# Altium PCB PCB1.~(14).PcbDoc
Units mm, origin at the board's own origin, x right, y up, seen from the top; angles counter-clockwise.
Board outline 152.4 x 101.6 mm, 2 copper layers (Top Layer, Bottom Layer); 19 components, 17 nets, 64 pads, 4 vias.
Unrouted connection lines stored in the file: 1.
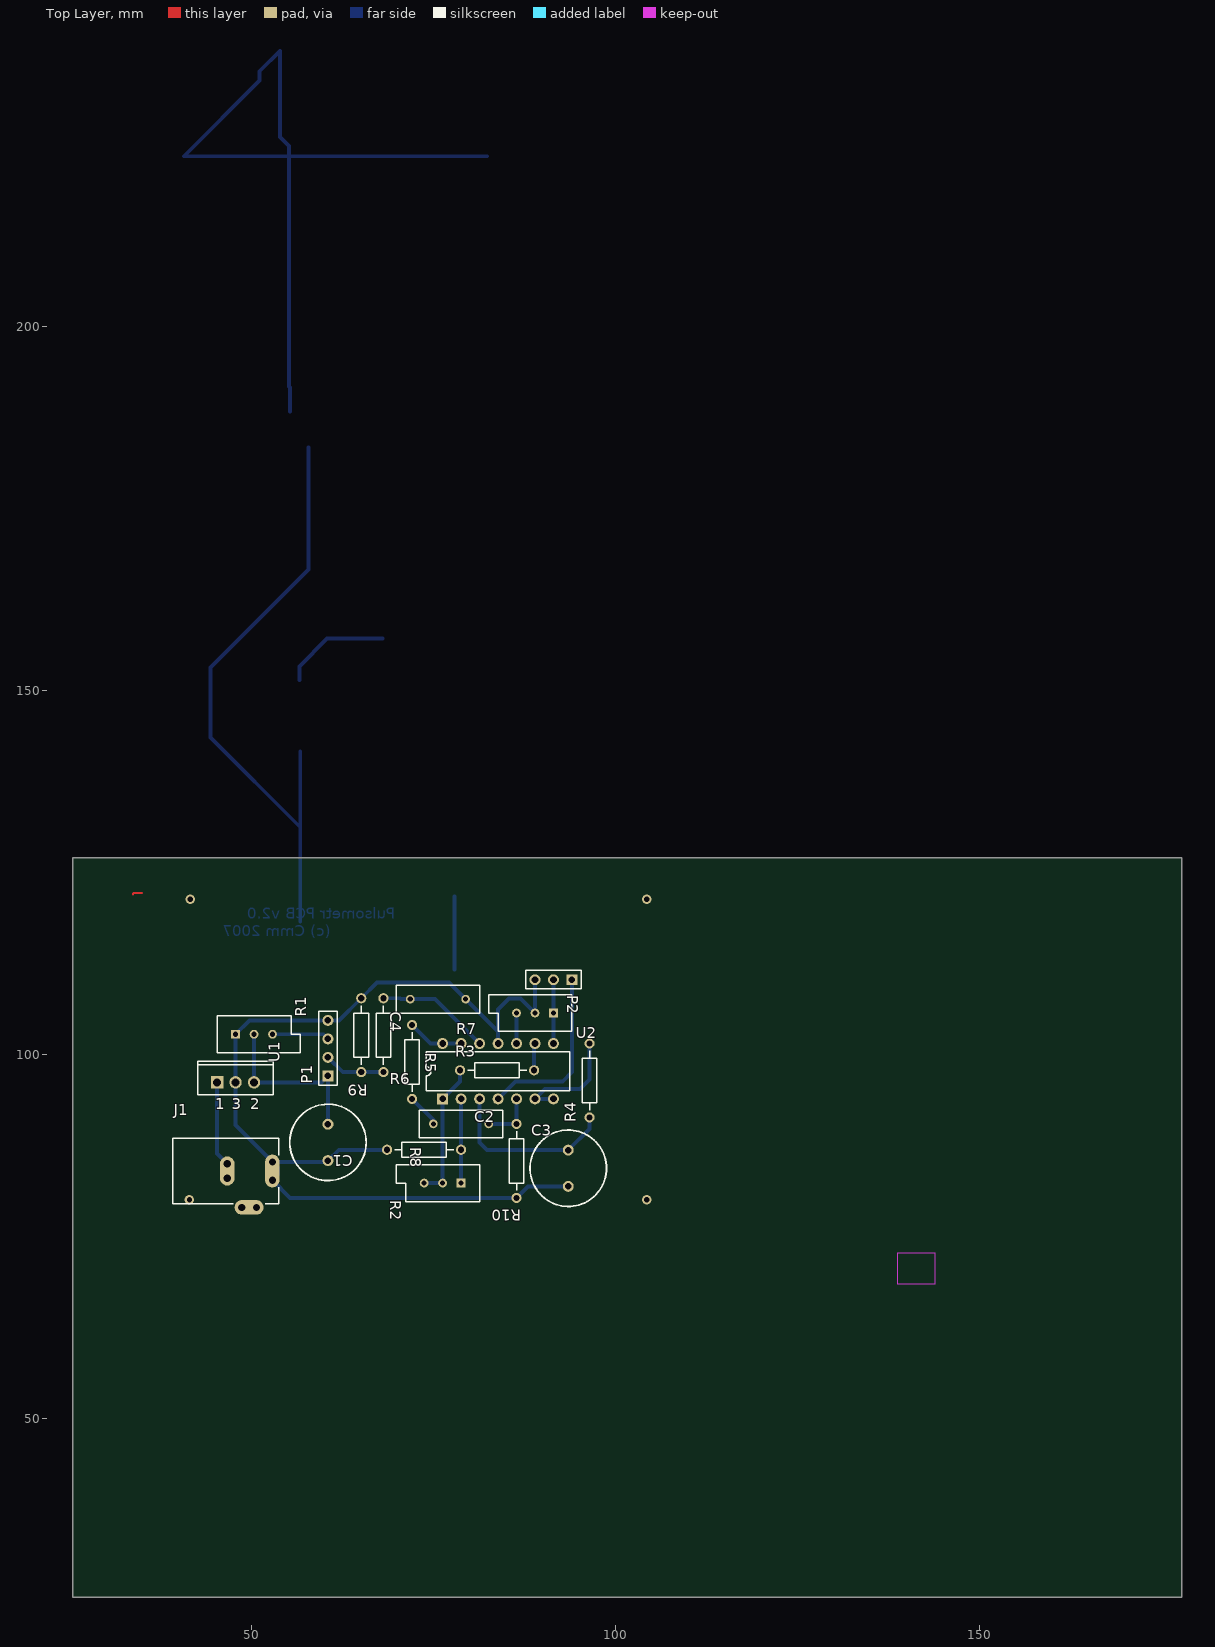
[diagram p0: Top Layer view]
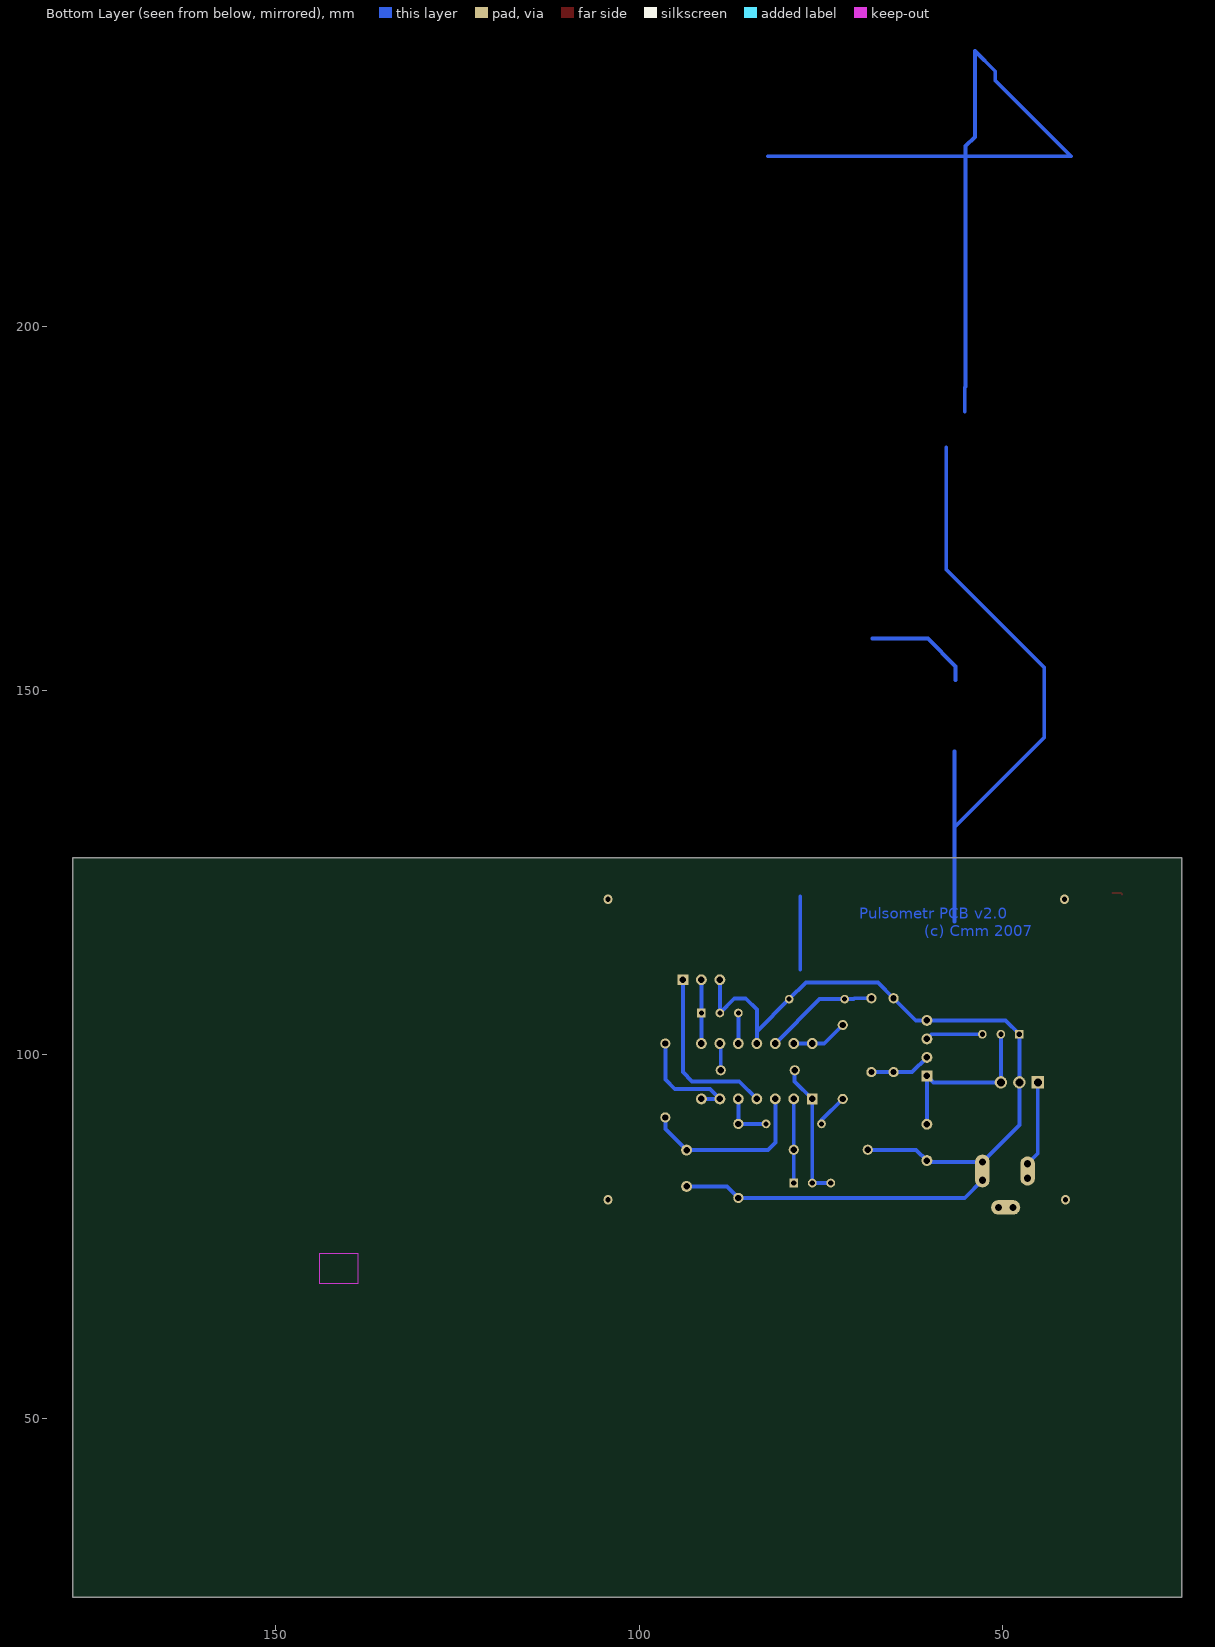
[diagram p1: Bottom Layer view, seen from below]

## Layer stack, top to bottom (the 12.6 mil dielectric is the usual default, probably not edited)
Top Layer: signal copper 0.0356
Dielectric: dielectric 0.32, FR-4, Dk 4.8
Bottom Layer: signal copper 0.0356

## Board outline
25.4,25.4 177.8,25.4 177.8,127 25.4,127

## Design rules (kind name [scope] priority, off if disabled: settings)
Clearance [All] p1: gap=0.254
ComponentClearance [All] p1: gap=0.254 collisioncheckmode=3 verticalgap=0.254
PolygonConnect [All] p1: connectstyle=Relief reliefconductorwidth=0.254 reliefentries=4 polygonreliefangle="90 Angle"
RoomDefinition Sheet1 [InComponentClass('Sheet1')] p1: confinementstyle=ConfineIn formatcopy=TRUE lockcomponents=FALSE outline 37.719,71.628 116.332,71.628 116.332,121.539 37.719,121.539
RoutingTopology [All] p1: topology=Daisy_Simple
RoutingVias [All] p1: holewidth=0.711 width=2 viastyle="Through Hole" minholewidth=0.711 minwidth=1.27 maxholewidth=0.711 maxwidth=2.27
SolderMaskExpansion [All] p1: expansion=0.102
TestPointUsage [All] p1: valid=0 allowmultiple=FALSE
Testpoint [All] p1: side=15 testpointundercomponent=TRUE minsize=1.016 maxsize=2.54 preferedsize=1.524 minholesize=0 maxholesize=1.016 preferedholesize=0.813 testpointgrid=0.025 style=1023 order=0123456789
Width [All] p1: maxlimit=1254 minlimit=0.254 preferedwidth=0.254 toplayer_maxwidth=1.254 toplayer_prefwidth=0.54 bottomlayer_minwidth=0.54 bottomlayer_prefwidth=0.54 minimp=50.000000 maximp=50.000000 favimp=50.000000
17 further rules are at their usual default settings.

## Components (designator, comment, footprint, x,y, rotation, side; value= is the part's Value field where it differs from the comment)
C1 "Cap Pol1" RB5-10.5 60.452,87.884 r90 top
C2 "Cap" RAD-0.3 78.74,90.424 r180 top
C3 "Cap Pol1" RB5-10.5 93.472,84.328 r270 top
C4 "Cap" RAD-0.3 75.565,107.569 r180 top
J1 "PWR2.5" KLD-0202 39.116,83.947 r0 top
P1 "Header 4" HDR1X4 60.452,97.028 r90 top
P2 "Header 3" HDR1X3 93.98,110.236 r180 top
R1 "RPot" VR5 50.292,102.743 r0 top
R2 "RPot" VR5 76.2,82.296 r180 top
R3 "Res2" AXIAL-0.4 83.693,97.79 r180 top
R4 "Res2" AXIAL-0.4 96.393,96.393 r90 top
R5 "Res2" AXIAL-0.4 72.009,98.933 r90 top
R6 "Res2" AXIAL-0.4 68.072,102.616 r270 top
R7 "RPot" VR5 88.9,105.664 r180 top
R8 "Res2" AXIAL-0.4 73.66,86.868 r180 top
R9 "Res2" AXIAL-0.4 65.024,102.616 r270 top
R10 "Res2" AXIAL-0.4 86.36,85.344 r270 top
U1 "L7812ABV" TO220ABN 47.752,96.139 r0 top
U2 "LM324AN" N14A 83.82,97.663 r0 top

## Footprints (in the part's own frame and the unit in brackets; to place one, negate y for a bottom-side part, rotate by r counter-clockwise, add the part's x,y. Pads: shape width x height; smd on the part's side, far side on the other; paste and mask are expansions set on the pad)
AXIAL-0.4 [mm] "Resistor; 2 Leads"
  round 1.4 hole 0.85: 1(-5.08,0) 2(5.08,0)
  silkscreen extent -4.06,-1.02 4.06,1.02
HDR1X3 [mm] "Connector; Header; 3 Position"
  rect 1.5x1.5 hole 0.9: 1(0,0)
  round 1.5 hole 0.9: 2(2.54,0) 3(5.08,0)
  silkscreen extent -1.27,-1.27 6.35,1.27
HDR1X4 [mm] "Connector; Header; 4 Position"
  rect 1.5x1.5 hole 0.9: 1(0,0)
  round 1.5 hole 0.9: 2(2.54,0) 3(5.08,0) 4(7.62,0)
  silkscreen extent -1.27,-1.27 8.89,1.27
KLD-0202 [mm] "DC Power Jack, 2.5mm, KLD Series, PCB Mount"
  oval 2x4.5 all layers, no hole: 1(13.7,0)
  round 1.5 hole 1: 1A(13.7,-1.25) 1B(13.7,1.25) 2A(7.5,-1) 2B(7.5,1) 3A(9.5,-5) 3B(11.5,-5)
  oval 2x4 all layers, no hole: 2(7.5,0)
  oval 4x2 all layers, no hole: 3(10.5,-5)
  silkscreen extent 0,-4.5 14.6,4.5
N14A [mm] "DIP; 14 Leads; Row Spacing 7.62 mm; Pitch 2.54 mm"
  rect 1.5x1.5 hole 0.9: 1(-7.62,-3.81)
  round 1.5 hole 0.9: 2(-5.08,-3.81) 3(-2.54,-3.81) 4(0,-3.81) 5(2.54,-3.81) 6(5.08,-3.81) 7(7.62,-3.81) 8(7.62,3.81) 9(5.08,3.81) 10(2.54,3.81) 11(0,3.81) 12(-2.54,3.81) 13(-5.08,3.81) 14(-7.62,3.81)
  silkscreen extent -9.85,-2.65 9.85,2.65
RAD-0.3 [mm] "Capacitor; 2 Leads"
  round 1.2 hole 0.7: 1(-3.81,0) 2(3.81,0)
  silkscreen extent -5.71,-1.91 5.71,1.91
RB5-10.5 [mm] "Motor, General Kind; 2 Leads"
  round 1.5 hole 0.9: 1(-2.5,0) 2(2.5,0)
  silkscreen extent -5.25,-5.25 5.25,5.25
TO220ABN [mm] "TO, Thru-Hole, Vertical, Heatsink Mounted; 3 In-Line Leads; Pitch 2.54 mm; Pin sequence 1, 3, 2"
  rect 1.7x1.7 hole 1.1: 1(-2.54,0)
  round 1.7 hole 1.1: 2(2.54,0) 3(0,0)
  silkscreen extent -5.2,-1.7 5.2,2.9
VR5 [mm] "Potentiometer; 3 Leads"
  rect 1.2x1.2 hole 0.7: 1(-2.54,0)
  round 1.2 hole 0.7: 2(0,0) 3(2.54,0)
  silkscreen extent -5.08,-2.54 6.35,2.54

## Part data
C1 C3: "Polarized Capacitor (Radial)"
C2 C4: "Capacitor"
J1: "Low Voltage Power Supply Connector"
P1: "Header, 4-Pin"
P2: library part "Header 2", "Header, 2-Pin"
R1 R2 R7: "Potentiometer"
R3 R4 R5 R6 R8 R9 R10: "Resistor"
U1: "Precision 1A Regulator"
U2: "Low-Power Quad Operational Amplifier"

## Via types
v1: diameter 1.27, hole 0.711, Top Layer to Bottom Layer, 4 vias

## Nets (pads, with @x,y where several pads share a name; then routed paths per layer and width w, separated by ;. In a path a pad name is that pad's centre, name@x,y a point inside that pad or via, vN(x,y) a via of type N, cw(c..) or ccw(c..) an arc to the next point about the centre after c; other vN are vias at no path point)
+5: C1.2 P1.1 P2.1 R1.2 U1.2 U2.4 | length 48.2
  Bottom Layer w0.54: R1.2 U1.2 59.563,96.139 P1.1 C1.2 ; U2.4 86.233,96.266 92.71,96.266 93.98,97.536 P2.1
GND: C1.1 C3.2 C4.1 J1.1 J1.1A J1.1B P1.4 P2.3 R1.1 R7.2 R8.2 R9.1 R10.2 U1.3 U2.11 | length 139.2
  Bottom Layer w0.54: R8.2@68.493,86.781 R8.2 61.936,86.868 C1.1 60.265,85.197 J1.1B ; U2.11 83.82,103.124 ; P2.3 R7.2 86.919,107.645 85.344,107.645 83.82,106.121 83.82,103.124 ; C3.2 87.924,81.828 R10.2 55.249,80.264 J1.1A 53.441,83.322 53.594,83.475 53.594,83.947 53.594,84.419 53.441,84.572 J1.1B ; J1.1B 47.752,90.261 U1.3 R1.1 49.657,104.648 P1.4 61.976,104.648 R9.1 67.183,109.855 77.089,109.855 C4.1 83.82,103.124
NetC2_1: C2.1 R10.1 U2.5 | length 7.2
  Bottom Layer w0.54: C2.1 R10.1 U2.5
NetC2_2: C2.2 R5.1 | length 4.6
  Bottom Layer w0.54: R5.1 74.93,90.932 C2.2
NetC3_1: C3.1 R4.1 U2.3 | length 24.3
  Bottom Layer w0.54: U2.3 81.28,87.844 82.296,86.828 C3.1 96.393,89.749 R4.1
NetC4_2: C4.2 R6.1 U2.12 | length 15.8
  Bottom Layer w0.54: R6.1 70.383,107.696 70.51,107.569 C4.2 75.184,107.569 U2.12
NetJ1_3: J1.3 J1.3A J1.3B | length 2
  Bottom Layer w0.54: J1.3A J1.3 J1.3B
NetP1_2: P1.2 R6.2 R9.2 | length 8.5
  Bottom Layer w0.54: P1.2 62.484,97.536 R9.2 R6.2
NetP1_3: P1.3 R1.3 | length 7.9
  Bottom Layer w0.54: R1.3 59.817,102.743 P1.3
NetP2_2: P2.2 R7.1 U2.8 | length 8.8
  Bottom Layer w0.54: U2.8 R7.1 P2.2
NetR2_1: R2.1 R8.1 U2.2 | length 11.6
  Bottom Layer w0.54: R2.1 R8.1 U2.2
NetR2_2: R2.2 R2.3 R3.2 U2.1 | length 19
  Bottom Layer w0.54: R2.3 R2.2 U2.1 78.613,96.266 R3.2
NetR3_1: R3.1 U2.9 | length 3.7
  Bottom Layer w0.54: R3.1 88.773,101.346 U2.9
NetR4_2: R4.2 U2.6 U2.7 | length 16.1
  Bottom Layer w0.54: U2.7 U2.6 90.272,95.225 95.098,95.225 96.393,96.52 R4.2
NetR5_2: R5.2 U2.13 U2.14 | length 7.8
  Bottom Layer w0.54: R5.2 74.549,101.473 U2.14 U2.13
NetR7_3: R7.3 U2.10 | length 4.2
  Bottom Layer w0.54: U2.10 R7.3
VCC: J1.2 J1.2A J1.2B U1.1 | length 15.2
  Bottom Layer w0.54: U1.1 45.212,86.351 J1.2B ; J1.2A 46.994,83.774 47.244,84.319 47.116,84.447 J1.2B ; J1.2 J1.2B
copper on no net: | length 228.8
  Top Layer w0.254: 33.655,121.92 33.655,122.047 33.782,122.174 34.925,122.174
  Bottom Layer w0.54: 55.245,188.341 55.245,191.643 55.118,191.77 55.118,224.79 53.848,226.06 53.848,237.871 51.054,235.077 51.054,233.807 40.64,223.393 82.296,223.393 ; 56.515,151.384 56.515,153.289 60.325,157.099 67.945,157.099 ; 56.642,118.237 56.642,141.605 ; 56.642,126.746 56.642,131.191 44.323,143.51 44.323,153.162 57.785,166.624 57.785,183.388 ; 77.851,111.633 77.851,121.666
  other v1: 41.402,80.01 104.267,80.01 41.529,121.285 104.267,121.285

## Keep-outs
Keep-Out Layer:
  rectangle: 138.684,68.453 143.891,72.644

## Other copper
Bottom Layer:
  text "Pulsometr PCB v2.0" at 69.723,118.618 h1.52
  text "(c) Cmm 2007" at 60.833,116.205 h1.52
